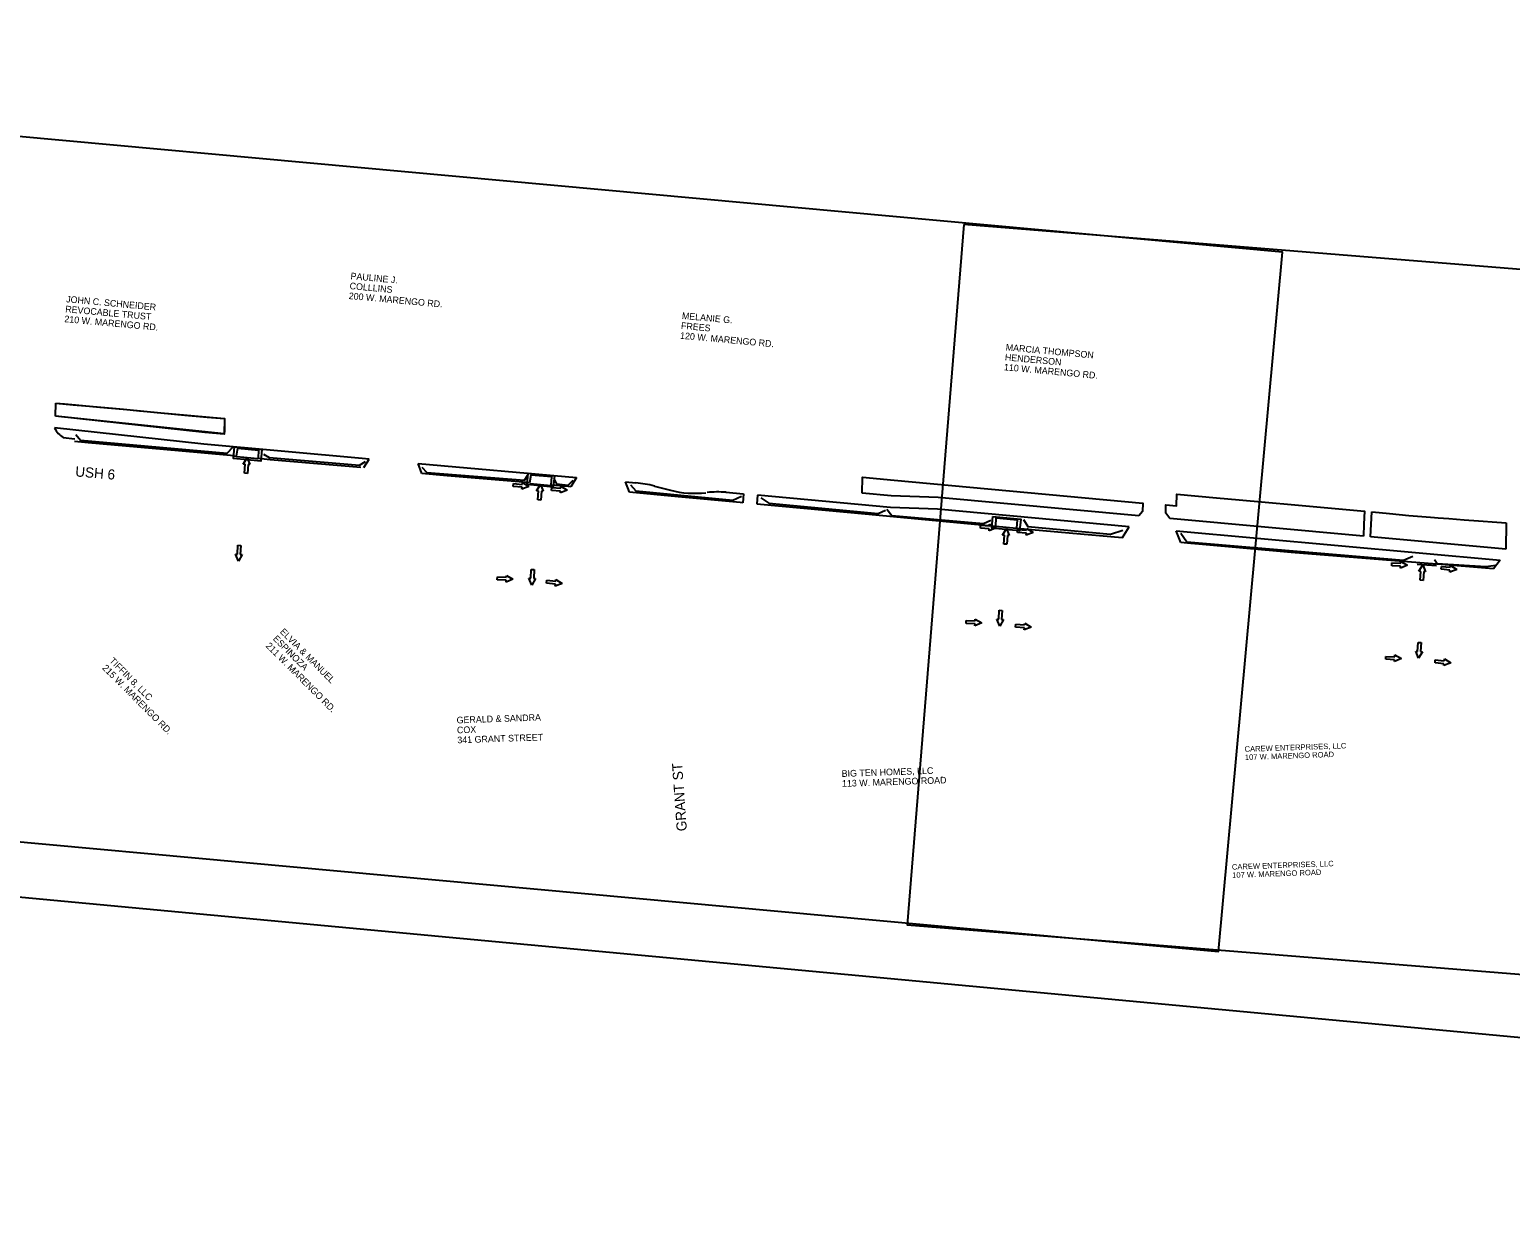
# Model space of a CAD drawing. Extents: x 20499351 to 20505779, y 7953198 to 7954637.
# Drawn here: x 20500313 to 20500946, y 7953707 to 7954215 of the extents above; entities that cross this region are included whole.
import ezdxf

# ---------------------------------------------------------------- set-up
doc = ezdxf.new("R2010")
doc.units = 0
for name, color, linetype in [('Draft_DNC', 7, 'Continuous'), ('dsnCellElements', 7, 'Continuous'), ('ErosionControl', 7, 'Continuous'), ('NamedBoundary', 7, 'Continuous'), ('Seeding', 7, 'Continuous'), ('Text', 7, 'Continuous')]:
    doc.layers.add(name, color=color, linetype=linetype)

msp = doc.modelspace()

# ---------------------------------------------------------------- linework, layer by layer
at = {"layer": 'Draft_DNC'}
msp.add_lwpolyline([(20501791.06, 7953833.84), (20501779.66, 7953706.56), (20499351.13, 7953933.78), (20499411.85, 7954636.65), (20501855.07, 7954405.25), (20501814.1, 7954091.19), (20501791.1, 7953834.34)], dxfattribs=at)
at = {"layer": 'dsnCellElements'}
for p, q in [((20500404.42, 7954029.15), (20500406.06, 7954031.9)), ((20500405.22, 7954029.09), (20500404.42, 7954029.15)), ((20500404.93, 7954025.28), (20500405.22, 7954029.09)), ((20500406.06, 7954031.9), (20500407.28, 7954028.93)), ((20500406.48, 7954028.99), (20500406.2, 7954025.19)), ((20500407.28, 7954028.93), (20500406.48, 7954028.99)), ((20500406.2, 7954025.19), (20500404.93, 7954025.28)), ((20500519.7, 7954019.57), (20500519.81, 7954020.84)), ((20500523.51, 7954019.26), (20500519.7, 7954019.57)), ((20500519.81, 7954020.84), (20500523.61, 7954020.52)), ((20500526.41, 7954019.65), (20500523.44, 7954018.46)), ((20500523.44, 7954018.46), (20500523.51, 7954019.26)), ((20500523.61, 7954020.52), (20500523.68, 7954021.32)), ((20500523.68, 7954021.32), (20500526.41, 7954019.65)), ((20500529.7, 7954017.77), (20500531.34, 7954020.51)), ((20500530.49, 7954017.71), (20500529.7, 7954017.77)), ((20500530.2, 7954013.9), (20500530.49, 7954017.71)), ((20500531.34, 7954020.51), (20500532.55, 7954017.55)), ((20500531.76, 7954017.61), (20500531.47, 7954013.81)), ((20500532.55, 7954017.55), (20500531.76, 7954017.61)), ((20500536.14, 7954017.89), (20500536.22, 7954019.16)), ((20500539.95, 7954017.64), (20500536.14, 7954017.89)), ((20500536.22, 7954019.16), (20500540.03, 7954018.91)), ((20500542.84, 7954018.09), (20500539.9, 7954016.85)), ((20500539.9, 7954016.85), (20500539.95, 7954017.64)), ((20500540.03, 7954018.91), (20500540.08, 7954019.71)), ((20500540.08, 7954019.71), (20500542.84, 7954018.09)), ((20500531.47, 7954013.81), (20500530.2, 7954013.9)), ((20500723.17, 7954002.75), (20500723.24, 7954003.54)), ((20500723.24, 7954003.54), (20500725.98, 7954001.89)), ((20500719.27, 7954001.78), (20500719.37, 7954003.05)), ((20500723.07, 7954001.48), (20500719.27, 7954001.78)), ((20500719.37, 7954003.05), (20500723.17, 7954002.75)), ((20500725.98, 7954001.89), (20500723.01, 7954000.69)), ((20500723.01, 7954000.69), (20500723.07, 7954001.48)), ((20500728.79, 7953998.87), (20500730.43, 7954001.61)), ((20500728.79, 7953998.87), (20500730.43, 7954001.61)), ((20500729.58, 7953998.81), (20500728.79, 7953998.87)), ((20500729.58, 7953998.81), (20500728.79, 7953998.87)), ((20500729.29, 7953995), (20500729.58, 7953998.81)), ((20500729.29, 7953995), (20500729.58, 7953998.81)), ((20500730.43, 7954001.61), (20500731.64, 7953998.65)), ((20500730.43, 7954001.61), (20500731.64, 7953998.65)), ((20500730.85, 7953998.71), (20500730.56, 7953994.9)), ((20500730.85, 7953998.71), (20500730.56, 7953994.9)), ((20500731.64, 7953998.65), (20500730.85, 7953998.71)), ((20500731.64, 7953998.65), (20500730.85, 7953998.71)), ((20500735.14, 7953999.97), (20500735.26, 7954001.24)), ((20500738.94, 7953999.61), (20500735.14, 7953999.97)), ((20500735.26, 7954001.24), (20500739.06, 7954000.88)), ((20500741.85, 7953999.98), (20500738.87, 7953998.82)), ((20500738.87, 7953998.82), (20500738.94, 7953999.61)), ((20500739.06, 7954000.88), (20500739.14, 7954001.67)), ((20500739.14, 7954001.67), (20500741.85, 7953999.98)), ((20500402.34, 7953987.77), (20500401.08, 7953990.71)), ((20500401.08, 7953990.71), (20500401.88, 7953990.66)), ((20500401.88, 7953990.66), (20500402.11, 7953994.47)), ((20500402.11, 7953994.47), (20500403.38, 7953994.4)), ((20500403.38, 7953994.4), (20500403.15, 7953990.59)), ((20500403.15, 7953990.59), (20500403.94, 7953990.54)), ((20500730.56, 7953994.9), (20500729.29, 7953995)), ((20500730.56, 7953994.9), (20500729.29, 7953995)), ((20500403.94, 7953990.54), (20500402.34, 7953987.77)), ((20500895, 7953985.73), (20500895.06, 7953987)), ((20500898.81, 7953985.54), (20500895, 7953985.73)), ((20500895.06, 7953987), (20500898.87, 7953986.81)), ((20500901.7, 7953986.03), (20500898.77, 7953984.75)), ((20500898.77, 7953984.75), (20500898.81, 7953985.54)), ((20500898.87, 7953986.81), (20500898.91, 7953987.6)), ((20500898.91, 7953987.6), (20500901.7, 7953986.03)), ((20500906.63, 7953983.4), (20500908.28, 7953986.15)), ((20500908.28, 7953986.15), (20500909.49, 7953983.19)), ((20500916.08, 7953984.23), (20500916.21, 7953985.49)), ((20500916.21, 7953985.49), (20500920.01, 7953985.11)), ((20500920.01, 7953985.11), (20500920.09, 7953985.9)), ((20500920.09, 7953985.9), (20500922.79, 7953984.19)), ((20500512.91, 7953979.77), (20500512.97, 7953981.04)), ((20500516.72, 7953979.58), (20500512.91, 7953979.77)), ((20500512.97, 7953981.04), (20500516.78, 7953980.85)), ((20500519.61, 7953980.07), (20500516.68, 7953978.78)), ((20500516.68, 7953978.78), (20500516.72, 7953979.58)), ((20500516.78, 7953980.85), (20500516.82, 7953981.64)), ((20500516.82, 7953981.64), (20500519.61, 7953980.07)), ((20500527.67, 7953977.49), (20500526.42, 7953980.43)), ((20500526.42, 7953980.43), (20500527.21, 7953980.39)), ((20500527.21, 7953980.39), (20500527.44, 7953984.19)), ((20500527.44, 7953984.19), (20500528.71, 7953984.12)), ((20500529.27, 7953980.26), (20500527.67, 7953977.49)), ((20500528.71, 7953984.12), (20500528.48, 7953980.31)), ((20500528.48, 7953980.31), (20500529.27, 7953980.26)), ((20500533.99, 7953978.27), (20500534.12, 7953979.53)), ((20500537.79, 7953977.88), (20500533.99, 7953978.27)), ((20500534.12, 7953979.53), (20500537.92, 7953979.15)), ((20500540.7, 7953978.23), (20500537.71, 7953977.09)), ((20500537.92, 7953979.15), (20500538, 7953979.94)), ((20500538, 7953979.94), (20500540.7, 7953978.23)), ((20500907.43, 7953983.34), (20500906.63, 7953983.4)), ((20500907.14, 7953979.54), (20500907.43, 7953983.34)), ((20500908.41, 7953979.44), (20500907.14, 7953979.54)), ((20500908.69, 7953983.25), (20500908.41, 7953979.44)), ((20500909.49, 7953983.19), (20500908.69, 7953983.25)), ((20500919.88, 7953983.85), (20500916.08, 7953984.23)), ((20500922.79, 7953984.19), (20500919.8, 7953983.06)), ((20500919.8, 7953983.06), (20500919.88, 7953983.85)), ((20500537.71, 7953977.09), (20500537.79, 7953977.88)), ((20500727.11, 7953962.91), (20500727.34, 7953966.72)), ((20500727.34, 7953966.72), (20500728.61, 7953966.64)), ((20500728.61, 7953966.64), (20500728.38, 7953962.83)), ((20500713.19, 7953961.08), (20500713.26, 7953962.35)), ((20500717, 7953960.89), (20500713.19, 7953961.08)), ((20500713.26, 7953962.35), (20500717.07, 7953962.16)), ((20500719.9, 7953961.39), (20500716.97, 7953960.1)), ((20500716.97, 7953960.1), (20500717, 7953960.89)), ((20500717.07, 7953962.16), (20500717.11, 7953962.96)), ((20500717.11, 7953962.96), (20500719.9, 7953961.39)), ((20500727.58, 7953960.01), (20500726.32, 7953962.95)), ((20500726.32, 7953962.95), (20500727.11, 7953962.91)), ((20500729.18, 7953962.78), (20500727.58, 7953960.01)), ((20500728.38, 7953962.83), (20500729.18, 7953962.78)), ((20500734.28, 7953959.58), (20500734.41, 7953960.85)), ((20500738.08, 7953959.2), (20500734.28, 7953959.58)), ((20500734.41, 7953960.85), (20500738.2, 7953960.47)), ((20500740.99, 7953959.55), (20500738, 7953958.41)), ((20500738, 7953958.41), (20500738.08, 7953959.2)), ((20500738.2, 7953960.47), (20500738.28, 7953961.26)), ((20500738.28, 7953961.26), (20500740.99, 7953959.55)), ((20500906.04, 7953949.17), (20500906.27, 7953952.98)), ((20500906.27, 7953952.98), (20500907.54, 7953952.9)), ((20500907.54, 7953952.9), (20500907.31, 7953949.09)), ((20500892.42, 7953945.78), (20500892.48, 7953947.05)), ((20500892.48, 7953947.05), (20500896.29, 7953946.86)), ((20500896.29, 7953946.86), (20500896.33, 7953947.65)), ((20500896.33, 7953947.65), (20500899.12, 7953946.08)), ((20500906.5, 7953946.27), (20500905.24, 7953949.22)), ((20500905.24, 7953949.22), (20500906.04, 7953949.17)), ((20500908.1, 7953949.04), (20500906.5, 7953946.27)), ((20500907.31, 7953949.09), (20500908.1, 7953949.04)), ((20500896.23, 7953945.59), (20500892.42, 7953945.78)), ((20500899.12, 7953946.08), (20500896.19, 7953944.79)), ((20500896.19, 7953944.79), (20500896.23, 7953945.59)), ((20500913.5, 7953944.28), (20500913.63, 7953945.54)), ((20500917.3, 7953943.89), (20500913.5, 7953944.28)), ((20500913.63, 7953945.54), (20500917.43, 7953945.16)), ((20500920.21, 7953944.24), (20500917.22, 7953943.1)), ((20500917.22, 7953943.1), (20500917.3, 7953943.89)), ((20500917.43, 7953945.16), (20500917.51, 7953945.95)), ((20500917.51, 7953945.95), (20500920.21, 7953944.24))]:
    msp.add_line(p, q, dxfattribs=at)
at = {"layer": 'ErosionControl'}
for p, q in [((20500324.27, 7954049.71), (20500324.36, 7954055.21)), ((20500388.03, 7954042.71), (20500324.26, 7954049.61)), ((20500327.53, 7954040.51), (20500332.45, 7954040)), ((20500410.61, 7954031.42), (20500401.65, 7954032.26)), ((20500455.96, 7954027.72), (20500458.13, 7954031.23)), ((20500480.7, 7954025.15), (20500479.06, 7954029.38)), ((20500479.06, 7954029.38), (20500546.74, 7954023.4)), ((20500546.74, 7954023.4), (20500544.32, 7954019.48)), ((20500535.86, 7954019.93), (20500526.96, 7954020.73)), ((20500567.66, 7954021.56), (20500572.08, 7954021.17)), ((20500569.39, 7954017.12), (20500567.66, 7954021.56)), ((20500580.08, 7954019.78), (20500586.97, 7954017.99)), ((20500580.08, 7954019.78), (20500586.97, 7954017.99)), ((20500610.62, 7954017.11), (20500618.11, 7954016.43)), ((20500610.62, 7954017.11), (20500618.11, 7954016.43)), ((20500618.11, 7954016.43), (20500617.76, 7954012.68)), ((20500624.08, 7954015.88), (20500623.74, 7954012.18)), ((20500734.72, 7954001.64), (20500725.82, 7954002.45)), ((20500780.06, 7953997.82), (20500782.9, 7954002.38)), ((20500804.94, 7953995.65), (20500802.92, 7954000.71)), ((20500802.92, 7954000.71), (20500941.37, 7953988.1)), ((20500914.18, 7953985.72), (20500905.86, 7953986.34)), ((20500938.49, 7953984.5), (20500914.44, 7953986.41)), ((20500941.37, 7953988.1), (20500938.49, 7953984.5))]:
    msp.add_line(p, q, dxfattribs=at)
for points in [[(20500324.36, 7954055.21), (20500331.8, 7954054.52), (20500338.76, 7954053.88), (20500348.54, 7954052.99), (20500353.19, 7954052.56), (20500363.4, 7954051.62), (20500379.43, 7954050.07), (20500389, 7954049.28), (20500396.46, 7954048.58), (20500396.38, 7954043.57), (20500396.3, 7954041.99), (20500388.03, 7954042.71)], [(20500458.13, 7954031.23), (20500455.16, 7954031.49), (20500387.53, 7954037.74), (20500323.76, 7954044.63)], [(20500332.9, 7954041.83), (20500334.81, 7954039.39), (20500397.6, 7954033.85), (20500400.15, 7954036.5)], [(20500332.36, 7954039.01), (20500338.11, 7954038.42), (20500376.81, 7954035), (20500398.91, 7954032.92), (20500401.56, 7954032.57)], [(20500401.56, 7954032.57), (20500402.02, 7954035.98), (20500410.93, 7954035.16), (20500410.79, 7954031.68)], [(20500410.79, 7954031.68), (20500415.96, 7954031.18), (20500454.63, 7954027.8)], [(20500413, 7954033.47), (20500415.52, 7954032), (20500454.11, 7954028.66), (20500456.66, 7954030.3)], [(20500480.66, 7954027.91), (20500482.85, 7954025.56), (20500524.55, 7954022.25), (20500526.08, 7954024.71)], [(20500526.73, 7954021.11), (20500524.03, 7954021.51), (20500491.46, 7954024.13), (20500480.7, 7954025.15)], [(20500536, 7954020.22), (20500536.27, 7954023.69), (20500527.31, 7954024.5), (20500526.73, 7954021.11)], [(20500537.09, 7954023.05), (20500538.17, 7954020.68), (20500543.13, 7954020.22), (20500545.28, 7954022.36)], [(20500544.32, 7954019.48), (20500543.24, 7954019.57), (20500536, 7954020.22)], [(20500617.76, 7954012.68), (20500616.65, 7954012.81), (20500590.16, 7954015.16), (20500569.4, 7954017.11)], [(20500569.79, 7954020.33), (20500572.06, 7954017.68), (20500613.58, 7954013.71), (20500617.23, 7954015.4)], [(20500782.91, 7954002.38), (20500701, 7954009.87), (20500680.89, 7954010.69), (20500624.08, 7954015.88)], [(20500623.74, 7954012.18), (20500670.05, 7954007.95), (20500713.72, 7954003.76), (20500725.83, 7954002.67)], [(20500625.52, 7954014.72), (20500628.89, 7954012.46), (20500675.64, 7954008.09), (20500678.69, 7954009.44)], [(20500679.33, 7954009.9), (20500681.43, 7954007.25), (20500720.6, 7954003.84), (20500723.79, 7954005.27)], [(20500725.83, 7954002.67), (20500726.09, 7954006.17), (20500735.05, 7954005.38), (20500734.74, 7954001.87)], [(20500737.78, 7954005.47), (20500739.56, 7954002.5), (20500774.94, 7953999.26), (20500780.2, 7954000.96)], [(20500734.74, 7954001.87), (20500757.16, 7953999.85), (20500779.83, 7953997.83), (20500780.06, 7953997.82)], [(20500804.89, 7953999.61), (20500807.42, 7953995.9), (20500900.04, 7953988.16), (20500904.07, 7953989.81)], [(20500812.66, 7953994.97), (20500809.18, 7953995.29), (20500804.94, 7953995.65)], [(20500910.58, 7953986.71), (20500852.08, 7953991.36), (20500812.66, 7953994.97)], [(20500914.44, 7953986.41), (20500914.44, 7953986.41), (20500910.58, 7953986.71), (20500910.58, 7953986.71)], [(20500913.35, 7953988.42), (20500914.35, 7953986.77), (20500935.16, 7953985.37), (20500939.44, 7953986.01)]]:
    msp.add_lwpolyline(points, dxfattribs=at)
for points in [[(20500400.67, 7954036.49), (20500412.3, 7954035.43), (20500411.85, 7954030.45), (20500400.21, 7954031.52)], [(20500526.17, 7954025.28), (20500537.34, 7954024.16), (20500536.85, 7954019.28), (20500525.68, 7954020.4)], [(20500724.66, 7954006.74), (20500736.51, 7954005.7), (20500736.07, 7954000.69), (20500724.21, 7954001.73)]]:
    msp.add_lwpolyline(points, close=True, dxfattribs=at)
for centre, radius, start, end in [((20500332.79, 7954049.01), 10, 205.99149, 238.26079), ((20500567.77, 7953972.37), 48.99, 75.43672, 84.95125), ((20500567.77, 7953972.37), 48.99, 75.43672, 84.95125), ((20500597.29, 7954057.68), 41.01, 255.43672, 276.57252), ((20500597.29, 7954057.68), 41.01, 255.43672, 276.57252), ((20500607.08, 7953978.28), 38.99, 84.77813, 96.57252), ((20500607.08, 7953978.28), 38.99, 84.77813, 96.57252)]:
    msp.add_arc(centre, radius, start, end, dxfattribs=at)
at = {"layer": 'NamedBoundary'}
for points in [[(20499911.73, 7954205.45), (20499884.39, 7953906.7), (20500820.97, 7953820.99), (20500848.31, 7954119.74)], [(20500712.21, 7954131.46), (20500688.08, 7953832.43), (20501625.52, 7953756.77), (20501649.66, 7954055.8)]]:
    msp.add_lwpolyline(points, close=True, dxfattribs=at)
at = {"layer": 'Seeding'}
for p, q in [((20500324.27, 7954049.71), (20500324.36, 7954055.21)), ((20500396.3, 7954042.06), (20500324.26, 7954049.61)), ((20500327.53, 7954040.51), (20500332.45, 7954040)), ((20500455.96, 7954027.72), (20500458.13, 7954031.23)), ((20500480.7, 7954025.15), (20500479.06, 7954029.38)), ((20500479.06, 7954029.38), (20500546.74, 7954023.4)), ((20500546.74, 7954023.4), (20500544.32, 7954019.48)), ((20500567.66, 7954021.56), (20500572.08, 7954021.17)), ((20500569.39, 7954017.12), (20500567.66, 7954021.56)), ((20500580.08, 7954019.78), (20500586.97, 7954017.99)), ((20500580.08, 7954019.78), (20500586.97, 7954017.99)), ((20500610.62, 7954017.11), (20500618.11, 7954016.43)), ((20500610.62, 7954017.11), (20500618.11, 7954016.43)), ((20500618.11, 7954016.43), (20500617.76, 7954012.68)), ((20500624.08, 7954015.88), (20500623.74, 7954012.18)), ((20500788.55, 7954008.89), (20500786.94, 7954007.03)), ((20500800.17, 7954005.98), (20500798.44, 7954008.26)), ((20500882.92, 7953998.44), (20500800.17, 7954005.98)), ((20500883.15, 7954003.51), (20500882.92, 7953998.44)), ((20500885.89, 7953998.17), (20500886.5, 7954008.74)), ((20500943.86, 7954004.02), (20500943.78, 7953992.9)), ((20500780.06, 7953997.82), (20500782.9, 7954002.38)), ((20500804.94, 7953995.65), (20500802.92, 7954000.71)), ((20500802.92, 7954000.71), (20500941.37, 7953988.1)), ((20500943.78, 7953992.9), (20500885.89, 7953998.17)), ((20500938.49, 7953984.5), (20500914.44, 7953986.41)), ((20500941.37, 7953988.1), (20500938.49, 7953984.5))]:
    msp.add_line(p, q, dxfattribs=at)
for points in [[(20500324.36, 7954055.21), (20500328.08, 7954054.87), (20500332.74, 7954054.44), (20500338.76, 7954053.88), (20500343.09, 7954053.49), (20500348.1, 7954053.03), (20500354.62, 7954052.43), (20500360.07, 7954051.93), (20500363.4, 7954051.62), (20500367.61, 7954051.21), (20500396.46, 7954048.58), (20500396.3, 7954042.06)], [(20500458.13, 7954031.23), (20500455.16, 7954031.49), (20500387.53, 7954037.74), (20500323.76, 7954044.63)], [(20500332.36, 7954039.01), (20500338.11, 7954038.42), (20500376.81, 7954035), (20500398.91, 7954032.92), (20500401.56, 7954032.57)], [(20500401.56, 7954032.57), (20500402.02, 7954035.98), (20500410.93, 7954035.16), (20500410.79, 7954031.68)], [(20500410.79, 7954031.68), (20500415.96, 7954031.18), (20500454.63, 7954027.8)], [(20500526.73, 7954021.11), (20500524.03, 7954021.51), (20500491.46, 7954024.13), (20500480.7, 7954025.15)], [(20500536, 7954020.22), (20500536.27, 7954023.69), (20500527.31, 7954024.5), (20500526.73, 7954021.11)], [(20500668.83, 7954016.81), (20500668.87, 7954023.54), (20500682.48, 7954022.29), (20500788.7, 7954012.52), (20500788.55, 7954008.89)], [(20500544.32, 7954019.48), (20500543.24, 7954019.57), (20500536, 7954020.22)], [(20500617.76, 7954012.68), (20500616.65, 7954012.81), (20500590.16, 7954015.16), (20500569.4, 7954017.11)], [(20500782.91, 7954002.38), (20500701, 7954009.87), (20500680.89, 7954010.69), (20500624.08, 7954015.88)], [(20500786.94, 7954007.03), (20500701.2, 7954014.87), (20500681.22, 7954015.68), (20500668.83, 7954016.81)], [(20500798.44, 7954008.26), (20500798.49, 7954011.78), (20500803.12, 7954011.36), (20500803.15, 7954016.3), (20500820.11, 7954014.82), (20500829.82, 7954013.93), (20500840.96, 7954012.91), (20500853.55, 7954011.76), (20500883.41, 7954009.02), (20500883.15, 7954003.51)], [(20500623.74, 7954012.18), (20500670.05, 7954007.95), (20500713.72, 7954003.76), (20500725.83, 7954002.67)], [(20500725.83, 7954002.67), (20500726.09, 7954006.17), (20500735.05, 7954005.38), (20500734.74, 7954001.87)], [(20500886.5, 7954008.74), (20500889.69, 7954008.45), (20500894.11, 7954008.04), (20500902.37, 7954007.28), (20500911.6, 7954006.49), (20500913.24, 7954006.36), (20500914.91, 7954006.22), (20500919.37, 7954005.88), (20500925.96, 7954005.38), (20500932.07, 7954004.91), (20500939.85, 7954004.32), (20500943.86, 7954004.02)], [(20500734.74, 7954001.87), (20500757.16, 7953999.85), (20500779.83, 7953997.83), (20500780.06, 7953997.82)], [(20500812.66, 7953994.97), (20500809.18, 7953995.29), (20500804.94, 7953995.65)], [(20500910.58, 7953986.71), (20500852.08, 7953991.36), (20500812.66, 7953994.97)], [(20500914.44, 7953986.41), (20500914.44, 7953986.41), (20500910.58, 7953986.71), (20500910.58, 7953986.71)]]:
    msp.add_lwpolyline(points, dxfattribs=at)
for centre, radius, start, end in [((20500332.79, 7954049.01), 10, 205.99149, 238.26079), ((20500567.77, 7953972.37), 48.99, 75.43672, 84.95125), ((20500567.77, 7953972.37), 48.99, 75.43672, 84.95125), ((20500597.29, 7954057.68), 41.01, 255.43672, 276.57252), ((20500597.29, 7954057.68), 41.01, 255.43672, 276.57252), ((20500607.08, 7953978.28), 38.99, 84.77813, 96.57252), ((20500607.08, 7953978.28), 38.99, 84.77813, 96.57252)]:
    msp.add_arc(centre, radius, start, end, dxfattribs=at)

# ---------------------------------------------------------------- texts
at = {"layer": 'Text'}
for s, height, rotation, p in [('PAULINE J.', 2.835, 354.76449, (20500450.14, 7954108.16)), ('COLLLINS', 2.835, 354.76449, (20500449.75, 7954103.93)), ('JOHN C. SCHNEIDER', 2.8346, 354.76449, (20500328.66, 7954098.29)), ('200 W. MARENGO RD.', 2.8346, 354.76449, (20500449.36, 7954099.69)), ('210 W. MARENGO RD.', 2.8346, 354.76449, (20500327.89, 7954089.82)), ('REVOCABLE TRUST', 2.8346, 354.76449, (20500328.28, 7954094.05)), ('MELANIE G.', 2.835, 354.76449, (20500591.69, 7954091.2)), ('120 W. MARENGO RD.', 2.8346, 354.76449, (20500590.91, 7954082.73)), ('FREES', 2.835, 354.76449, (20500591.3, 7954086.97)), ('MARCIA THOMPSON', 2.8346, 354.76449, (20500730.04, 7954077.72)), ('HENDERSON', 2.835, 354.76449, (20500729.66, 7954073.48)), ('110 W. MARENGO RD.', 2.8346, 354.76449, (20500729.27, 7954069.25)), ('USH 6', 4.32, 355.08047, (20500332.51, 7954023.94)), ('ELVIA & MANUEL', 2.8346, 314.98356, (20500419.85, 7953957.32)), ('211 W. MARENGO RD.', 2.8346, 314.98356, (20500413.83, 7953951.31)), ('ESPINOZA', 2.835, 314.98356, (20500416.84, 7953954.32)), ('TIFFIN 8, LLC', 2.8346, 314.98356, (20500346.96, 7953944.88)), ('215 W. MARENGO RD.', 2.8346, 314.98356, (20500343.95, 7953941.88)), ('GERALD & SANDRA', 2.8346, 1.96447, (20500495.6, 7953918.39)), ('COX', 2.835, 1.96447, (20500495.75, 7953914.14)), ('341 GRANT STREET', 2.8346, 1.96447, (20500495.89, 7953909.89)), ('CAREW ENTERPRISES, LLC', 2.3424, 1.96447, (20500832.2, 7953906.26)), ('107 W. MARENGO ROAD', 2.3424, 1.96447, (20500832.32, 7953902.75)), ('GRANT ST', 4.32, 94.09505, (20500593.93, 7953872.52)), ('BIG TEN HOMES, LLC', 2.8346, 1.96447, (20500660.08, 7953895.54)), ('113 W. MARENGO ROAD', 2.8346, 1.96447, (20500660.22, 7953891.3)), ('CAREW ENTERPRISES, LLC', 2.3424, 1.96447, (20500826.77, 7953855.92)), ('107 W. MARENGO ROAD', 2.3424, 1.96447, (20500826.89, 7953852.41))]:
    msp.add_text(s, height=height, rotation=rotation, dxfattribs=at).set_placement(p)

doc.saveas('drawing.dxf')
